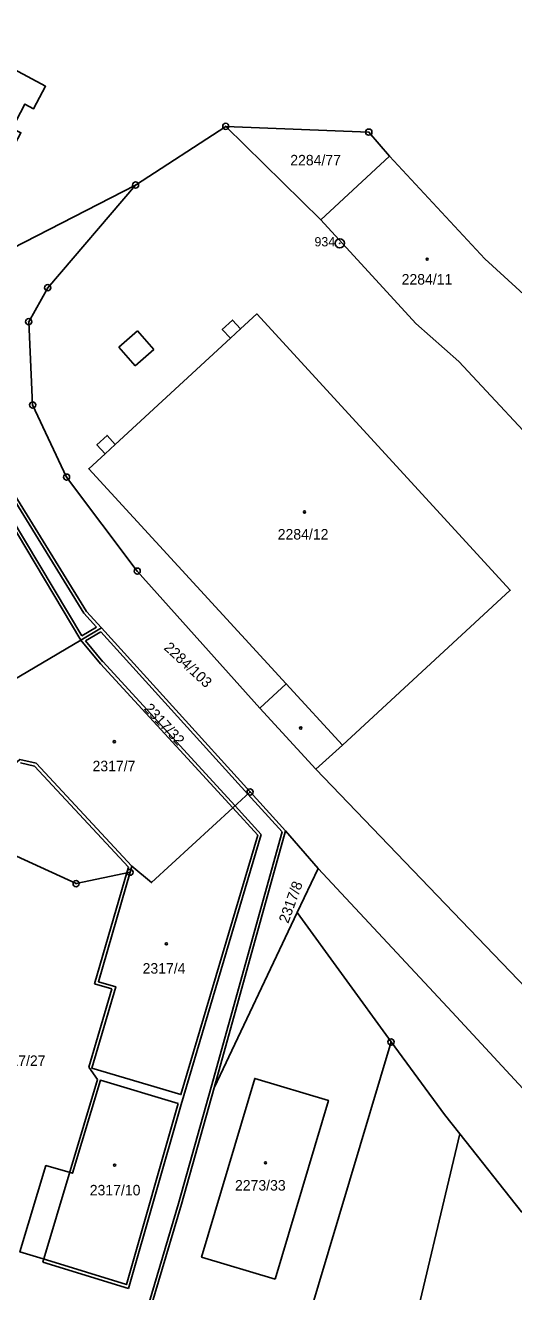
# Model space of a CAD drawing. Extents: x -733394 to -722299, y -1082822 to -1075049.
# Drawn here: x -729003.5 to -728924.3, y -1080318.9 to -1080113.9 of the extents above; entities that cross this region are included whole.
import ezdxf

# ---------------------------------------------------------------- set-up
doc = ezdxf.new("R2010")
doc.units = 0
for name, color, linetype in [('Hranice parcel', 7, 'Continuous'), ('Parcelní čísla', 7, 'Continuous'), ('Vnitřní kresba', 7, 'Continuous'), ('Značky bodu BP', 7, 'Continuous'), ('Značky budov', 7, 'Continuous')]:
    doc.layers.add(name, color=color, linetype=linetype)

msp = doc.modelspace()

# ---------------------------------------------------------------- linework, layer by layer
at = {"layer": 'Hranice parcel'}
for p, q in [((-728985.65, -1080139.73), (-728971.02, -1080130.23)), ((-728971.02, -1080130.23), (-728955.63, -1080145.36)), ((-728944.46, -1080135.06), (-728955.63, -1080145.36)), ((-729005.67, -1080149.99), (-728985.65, -1080139.73)), ((-728994.54, -1080213.44), (-728991.18, -1080211.45)), ((-728967.08, -1080238.02), (-728991.18, -1080211.45)), ((-729010.5, -1080222.88), (-728994.54, -1080213.44)), ((-728965.51, -1080224.44), (-728956.4, -1080234.35)), ((-728956.4, -1080234.35), (-728897.91, -1080295.2)), ((-728967.08, -1080238.02), (-728969.89, -1080240.6)), ((-728961.34, -1080244.34), (-728967.08, -1080238.02)), ((-728961.34, -1080244.34), (-728972.93, -1080285.94)), ((-728956.05, -1080250.41), (-728961.34, -1080244.34)), ((-728986.25, -1080250.06), (-728986.53, -1080251.02)), ((-728956.05, -1080250.41), (-728959.44, -1080257.55)), ((-728959.44, -1080257.55), (-728972.93, -1080285.94)), ((-728944.23, -1080278.5), (-728959.44, -1080257.55)), ((-728961.72, -1080336.96), (-728944.23, -1080278.5))]:
    msp.add_line(p, q, dxfattribs=at)
for points in [[(-729022.82, -1080121.37), (-729019.38, -1080123.2), (-729017.31, -1080119.32), (-729020.7, -1080117.52), (-729018.75, -1080113.87), (-729000.24, -1080123.73), (-729002.18, -1080127.38), (-729003.59, -1080126.63), (-729005.66, -1080130.57), (-729004.25, -1080131.26), (-729006.27, -1080135.06), (-729024.84, -1080125.16), (-729022.82, -1080121.37)], [(-728971.02, -1080130.23), (-728947.83, -1080131.17), (-728944.46, -1080135.06)], [(-728944.46, -1080135.06), (-728929.01, -1080151.66), (-728922.12, -1080158)], [(-728985.65, -1080139.73), (-728999.9, -1080156.36), (-729002.97, -1080161.87), (-729002.34, -1080175.35), (-728996.84, -1080187.03), (-728985.38, -1080202.26), (-728965.51, -1080224.44)], [(-728955.63, -1080145.36), (-728940.22, -1080162.17), (-728933.21, -1080168.29), (-728917.64, -1080185.07)], [(-728991.18, -1080211.45), (-728993.6, -1080208.79), (-729005.64, -1080189.23), (-729014.46, -1080172.93), (-729011.87, -1080171.31), (-729011.58, -1080164.95), (-729009.8, -1080157.44), (-729008.52, -1080154.68), (-729006.1, -1080151.62), (-729005.67, -1080149.99)], [(-728956.4, -1080234.35), (-728952.1, -1080230.42), (-728924.89, -1080205.35), (-728965.99, -1080160.61), (-728968.62, -1080163.03), (-728969.94, -1080161.6), (-728971.59, -1080163.12), (-728970.28, -1080164.55), (-728988.94, -1080181.73), (-728990.26, -1080180.29), (-728991.92, -1080181.82), (-728990.59, -1080183.25), (-728993.23, -1080185.67), (-728961.21, -1080220.49), (-728965.51, -1080224.44)], [(-728994.54, -1080213.44), (-729018.15, -1080173.95), (-729033.91, -1080183.78), (-729010.5, -1080222.88)], [(-728969.89, -1080240.6), (-728991.33, -1080217.26), (-728994.54, -1080213.44)], [(-729010.5, -1080222.88), (-729008.53, -1080226.17), (-729006.26, -1080228.68), (-729008.93, -1080232), (-729010.31, -1080235.27), (-729007.17, -1080236.99), (-729006.01, -1080234.11), (-729004.44, -1080232.77), (-729001.76, -1080233.37), (-728986.25, -1080250.06)], [(-728986.53, -1080251.02), (-728995.29, -1080252.86), (-729024.94, -1080239.32)], [(-728986.53, -1080251.02), (-728991.68, -1080268.75), (-728988.86, -1080269.57), (-728992.76, -1080282.75), (-728978.3, -1080287.04), (-728965.83, -1080245.03), (-728969.89, -1080240.6)], [(-728969.89, -1080240.6), (-728983.06, -1080252.69), (-728986.25, -1080250.06)], [(-728907.35, -1080302.77), (-728934.3, -1080273.69), (-728956.05, -1080250.41)], [(-728944.23, -1080278.5), (-728935.54, -1080290.26), (-728933.05, -1080293.4)], [(-728978.72, -1080288.47), (-728991.35, -1080284.7), (-728995.86, -1080299.76), (-729000.18, -1080298.52), (-729004.41, -1080312.5), (-729000.07, -1080313.81), (-728987.13, -1080317.8), (-728978.72, -1080288.47)], [(-728963.02, -1080316.94), (-728974.94, -1080313.34), (-728966.33, -1080284.42), (-728954.39, -1080287.98), (-728963.02, -1080316.94)], [(-728972.93, -1080285.94), (-728978.19, -1080304.8), (-728985.67, -1080329.8)], [(-729013.62, -1080628.25), (-729013.56, -1080627.97), (-729008.32, -1080607.57), (-728996.73, -1080558.16), (-728976.65, -1080477.82), (-728963.72, -1080422.19), (-728941.79, -1080329.98), (-728933.05, -1080293.4)], [(-728933.05, -1080293.4), (-728923.06, -1080306.01), (-728918.62, -1080310.72)]]:
    msp.add_lwpolyline(points, dxfattribs=at)
at = {"layer": 'Vnitřní kresba'}
for p, q in [((-728988.35, -1080166.01), (-728985.34, -1080163.35)), ((-728985.34, -1080163.35), (-728982.69, -1080166.36)), ((-728970.28, -1080164.55), (-728968.62, -1080163.03)), ((-728985.7, -1080169.03), (-728988.35, -1080166.01)), ((-728982.69, -1080166.36), (-728985.7, -1080169.03)), ((-729017.98, -1080173.25), (-728994.37, -1080212.76)), ((-728990.59, -1080183.25), (-728988.94, -1080181.73)), ((-729006.08, -1080189.47), (-728994.03, -1080209.05)), ((-728994.03, -1080209.05), (-728991.96, -1080211.33)), ((-728994.37, -1080212.76), (-728991.96, -1080211.33)), ((-728993.78, -1080213.57), (-728991.28, -1080212.09)), ((-728993.78, -1080213.57), (-728990.95, -1080216.94)), ((-728991.28, -1080212.09), (-728967.45, -1080238.36)), ((-728990.96, -1080216.92), (-728969.52, -1080240.26)), ((-728961.21, -1080220.49), (-728952.1, -1080230.42)), ((-729002.02, -1080233.82), (-729004.31, -1080233.31)), ((-729002.02, -1080233.82), (-728986.81, -1080250.2)), ((-728967.45, -1080238.36), (-728961.9, -1080244.47)), ((-728969.52, -1080240.26), (-728965.27, -1080244.9)), ((-728961.9, -1080244.47), (-728973.41, -1080285.81)), ((-728965.27, -1080244.9), (-728977.82, -1080287.18)), ((-728992.3, -1080269.09), (-728987.01, -1080250.88)), ((-728987.01, -1080250.88), (-728986.81, -1080250.2)), ((-728989.48, -1080269.91), (-728992.3, -1080269.09)), ((-728993.24, -1080282.61), (-728989.48, -1080269.91)), ((-728993.24, -1080282.61), (-728991.83, -1080284.56)), ((-729000.69, -1080314.14), (-728991.83, -1080284.56)), ((-728973.41, -1080285.81), (-728978.67, -1080304.67)), ((-728978.24, -1080288.61), (-728977.82, -1080287.18)), ((-728978.24, -1080288.61), (-728986.79, -1080318.43)), ((-728978.67, -1080304.66), (-728986.03, -1080329.26)), ((-728986.79, -1080318.43), (-729000.69, -1080314.14))]:
    msp.add_line(p, q, dxfattribs=at)
at = {"layer": 'Značky bodu BP'}
for centre, radius in [((-728971.02, -1080130.23), 0.5), ((-728971.02, -1080130.23), 0.0303), ((-728947.83, -1080131.17), 0.5), ((-728947.83, -1080131.17), 0.0303), ((-728985.65, -1080139.73), 0.5), ((-728985.65, -1080139.73), 0.0303), ((-728952.54, -1080149.17), 0.75), ((-728952.54, -1080149.17), 0.03), ((-728999.9, -1080156.36), 0.5), ((-728999.9, -1080156.36), 0.0303), ((-729002.97, -1080161.87), 0.5), ((-729002.97, -1080161.87), 0.0303), ((-729002.34, -1080175.35), 0.5), ((-729002.34, -1080175.35), 0.0303), ((-728996.84, -1080187.03), 0.5), ((-728996.84, -1080187.03), 0.0303), ((-728985.38, -1080202.26), 0.5), ((-728985.38, -1080202.26), 0.0303), ((-728967.08, -1080238.02), 0.5), ((-728967.08, -1080238.02), 0.0303), ((-728986.53, -1080251.02), 0.5), ((-728986.53, -1080251.02), 0.0303), ((-728995.29, -1080252.86), 0.5), ((-728995.29, -1080252.86), 0.0303), ((-728944.23, -1080278.5), 0.5), ((-728944.23, -1080278.5), 0.0303)]:
    msp.add_circle(centre, radius, dxfattribs=at)
at = {"layer": 'Značky budov'}
for centre in [(-728938.38, -1080151.73), (-728958.27, -1080192.67), (-728958.87, -1080227.67), (-728989.1, -1080229.88), (-728980.65, -1080262.62), (-728964.59, -1080298.08), (-728989.04, -1080298.45)]:
    msp.add_circle(centre, 0.175, dxfattribs=at)

# ---------------------------------------------------------------- texts
at = {"layer": 'Parcelní čísla'}
for s, p in [('2284/77', (-728960.57, -1080136.55)), ('2284/11', (-728942.51, -1080155.85)), ('2284/12', (-728962.6, -1080197.14)), ('2317/7', (-728992.63, -1080234.67)), ('2317/4', (-728984.51, -1080267.44)), ('2317/27', (-729008.47, -1080282.39)), ('2317/10', (-728993.08, -1080303.35)), ('2273/33', (-728969.53, -1080302.57))]:
    msp.add_text(s, height=1.7, dxfattribs=at).set_placement(p)
for s, rotation, p in [('2284/103', 317, (-728981.18, -1080214.81)), ('2317/32', 313, (-728984.39, -1080224.62)), ('2317/8', 70, (-728960.9, -1080259.4))]:
    msp.add_text(s, height=1.7, rotation=rotation, dxfattribs=at).set_placement(p)
at = {"layer": 'Značky bodu BP'}
msp.add_text('934', height=1.5, dxfattribs=at).set_placement((-728956.64, -1080149.67))

doc.saveas('drawing.dxf')
